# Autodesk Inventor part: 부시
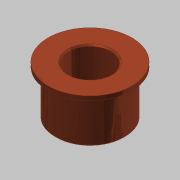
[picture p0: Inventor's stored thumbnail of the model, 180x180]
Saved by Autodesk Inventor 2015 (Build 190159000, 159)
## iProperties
Created: 2015-10
Part Number: 부시
Document SubType Name: Modeling
Designer: mdu
Density: 7.86 g/cm^3
Material: 강철, 연강
Mass: 246.97 g
Surface Area: 129.264 cm^2
Volume: 31.4212 cm^3
Appearance: 구리 - 새틴
Author: mdu
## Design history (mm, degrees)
sketch "스케치1"
  geometry: C1 r 31 at (0, 0) reference; C2 r 25 at (0, 0) reference; C3 r 30 at (0, 0) reference; 1 further point
  node "참조1"
  node "참조2"
  node "참조4"
extrude "돌출1" new body sketch "스케치1" distance "d0" = 3; taper "d1" = 0 deg
extrude "돌출2" join sketch "스케치1" distance "d2" = 35; taper "d3" = 0 deg
chamfer "모따기1" distance "d6" = 1; stored, may be unused: second distance "d7" = 2, angle "d8" = 45 deg
sketch "스케치3"
  geometry: C1 r 15 at (0, 0); 1 further point
  constraints: 1 centre point, 1 coincident
  dimensions: "d13" = 30 diameter of C1
extrude "돌출4" cut sketch "스케치3" stored distance "d14" = 10; taper "d15" = 0 deg
chamfer "모따기3" distance "d16" = 1; stored, may be unused: second distance "d17" = 2, angle "d18" = 45 deg
node "솔리드1"
